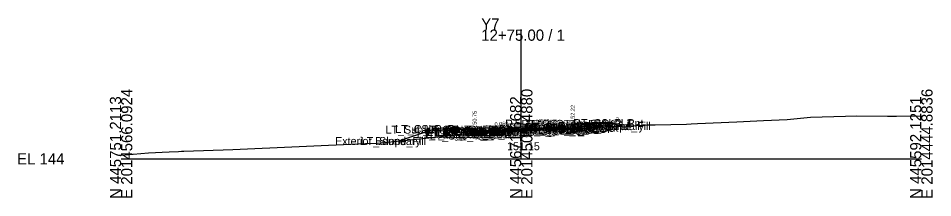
# Model space of a CAD drawing. Extents: x -26 to 203, y -10 to 7527.
# Drawn here: x -25.7 to 202.8, y 5490.3 to 5535.1 of the extents above; entities that cross this region are included whole.
import ezdxf

# ---------------------------------------------------------------- set-up
doc = ezdxf.new("R2010")
doc.units = 0
for name, color, linetype in [('Exist CMT Pavement', 7, 'Continuous'), ('Exist Cross Section Cell', 7, 'Continuous'), ('Exist XS Center Line Elevation Label', 7, 'Continuous'), ('Exist XS Ground Line', 7, 'Continuous'), ('Prop CMT Conc Surface', 7, 'Continuous'), ('Prop CMT Concrete Structures', 7, 'Continuous'), ('Prop CMT Pvmt Course 1', 7, 'Continuous'), ('Prop CMT Pvmt Course 1 CG', 7, 'Continuous'), ('Prop CMT Pvmt Course 1 Wedge', 7, 'Continuous'), ('Prop CMT Pvmt Course 2', 7, 'Continuous'), ('Prop CMT Pvmt Course 2 Wedge', 7, 'Continuous'), ('Prop CMT Pvmt Course 3', 7, 'Continuous'), ('Prop CMT Pvmt Course 3 Wedge', 7, 'Continuous'), ('Prop CMT Pvmt Surface', 7, 'Continuous'), ('Prop CMT Pvmt Wedge Surface 1', 7, 'Continuous'), ('Prop CMT Pvmt Wedge Surface 2', 7, 'Continuous'), ('Prop CMT Pvmt Wedge Surface 3', 7, 'Continuous'), ('Prop CMT Slope Grass', 7, 'Continuous'), ('Prop CMT Subgrade Earthwork', 7, 'Continuous'), ('Prop XS Earthwork Shape', 7, 'Continuous'), ('Prop XS Hydro Elevations', 7, 'Continuous'), ('Prop XS SE Text', 7, 'Continuous'), ('Prop XS Side Slope Text', 7, 'Continuous'), ('Scratch_Level_0', 7, 'Continuous')]:
    doc.layers.add(name, color=color, linetype=linetype)

msp = doc.modelspace()

# ---------------------------------------------------------------- linework, layer by layer
at = {"layer": 'Exist CMT Pavement'}
msp.add_lwpolyline([(91.4, 5506.74), (96.26, 5507.07), (98.92, 5507.12), (100, 5507.15), (101.1, 5507.18), (101.96, 5507.19), (104.5, 5507.18), (107.13, 5507.22)], dxfattribs=at)
at = {"layer": 'Exist Cross Section Cell'}
for p, q in [((100, 5500), (100, 5532.27)), ((0, 5500), (100, 5500)), ((100, 5500), (200, 5500))]:
    msp.add_line(p, q, dxfattribs=at)
at = {"layer": 'Exist XS Ground Line'}
msp.add_lwpolyline([(0, 5500.89), (2.98, 5501.16), (6.88, 5501.48), (12.01, 5501.74), (14.33, 5501.86), (15.1, 5501.89), (15.66, 5501.91), (27.95, 5502.3), (61.07, 5503.8), (63.97, 5503.95), (65.85, 5504.08), (78.42, 5505.37), (87.42, 5506.45), (88.06, 5506.45), (88.69, 5506.55), (96.26, 5507.07), (98.92, 5507.12), (100, 5507.15), (101.1, 5507.18), (101.96, 5507.19), (104.5, 5507.18), (108.95, 5507.25), (113.1, 5507.43), (122.06, 5508.05), (123.08, 5508.08), (124, 5508.12), (130.78, 5508.4), (131.63, 5508.45), (132.27, 5508.47), (133.47, 5508.48), (141.29, 5508.68), (142.47, 5508.73), (144.03, 5508.82), (153.86, 5509.27), (160.53, 5509.53), (166.43, 5509.84), (172.31, 5510.37), (181.08, 5510.68), (183.83, 5510.71), (191.53, 5510.62), (193.76, 5510.64), (200, 5510.76)], dxfattribs=at)
at = {"layer": 'Prop CMT Conc Surface'}
for points in [[(110.88, 5508.18), (112.88, 5508.22)], [(112.88, 5508.22), (112.88, 5508.72), (113.38, 5508.72)], [(88.35, 5506.75), (88.35, 5507.25), (87.85, 5507.25)], [(90.35, 5506.95), (88.35, 5506.75)]]:
    msp.add_lwpolyline(points, dxfattribs=at)
at = {"layer": 'Prop CMT Concrete Structures'}
for points in [[(110.88, 5508.18), (112.88, 5508.22), (112.88, 5508.72), (113.38, 5508.72)], [(113.38, 5508.72), (113.38, 5507.74), (110.88, 5507.59)], [(110.88, 5507.59), (110.88, 5508.18)], [(90.35, 5506.95), (88.35, 5506.75), (88.35, 5507.25), (87.85, 5507.25)], [(87.85, 5507.25), (87.85, 5506.21), (90.35, 5506.36)], [(90.35, 5506.36), (90.35, 5506.95)]]:
    msp.add_lwpolyline(points, dxfattribs=at)
at = {"layer": 'Prop CMT Pvmt Course 1'}
for points in [[(100, 5507.52), (110.88, 5508.18)], [(107.13, 5507.83), (100, 5507.4)], [(110.88, 5507.93), (107.13, 5507.7)], [(107.13, 5507.7), (107.13, 5507.83)], [(110.88, 5508.18), (110.88, 5507.93)], [(100, 5507.52), (90.35, 5506.95)], [(90.35, 5506.95), (90.35, 5506.7)], [(90.35, 5506.7), (91.4, 5506.76)], [(91.4, 5506.88), (100, 5507.4)], [(91.4, 5506.76), (91.4, 5506.88)], [(100, 5507.27), (100, 5507.52)], [(100, 5507.27), (100, 5507.52)], [(100, 5507.4), (100, 5507.27), (100, 5507.27)], [(100, 5507.4), (100, 5507.27), (100, 5507.27)]]:
    msp.add_lwpolyline(points, dxfattribs=at)
at = {"layer": 'Prop CMT Pvmt Course 1 CG'}
for points in [[(110.88, 5507.59), (113.88, 5507.77), (114.19, 5507.46)], [(90.35, 5506.36), (87.35, 5506.18), (87, 5505.83)], [(87, 5505.83), (90.35, 5506.03)], [(90.35, 5506.03), (90.35, 5506.36)], [(110.88, 5507.26), (110.88, 5507.59)], [(114.19, 5507.46), (110.88, 5507.26)]]:
    msp.add_lwpolyline(points, dxfattribs=at)
at = {"layer": 'Prop CMT Pvmt Course 1 Wedge'}
for points in [[(100, 5507.4), (107.13, 5507.83)], [(100, 5507.4), (91.4, 5506.88)]]:
    msp.add_lwpolyline(points, dxfattribs=at)
at = {"layer": 'Prop CMT Pvmt Course 2'}
for points in [[(107.13, 5507.7), (110.88, 5507.93)], [(107.13, 5507.37), (107.13, 5507.7)], [(110.88, 5507.93), (110.88, 5507.59)], [(91.4, 5506.76), (90.35, 5506.7)], [(90.35, 5506.7), (90.35, 5506.36)], [(90.35, 5506.36), (91.4, 5506.43)], [(91.4, 5506.43), (91.4, 5506.76)], [(110.88, 5507.59), (107.13, 5507.37)]]:
    msp.add_lwpolyline(points, dxfattribs=at)
at = {"layer": 'Prop CMT Pvmt Course 2 Wedge'}
for points in [[(100, 5507.27), (107.13, 5507.7)], [(100, 5507.27), (91.4, 5506.76)]]:
    msp.add_lwpolyline(points, dxfattribs=at)
at = {"layer": 'Prop CMT Pvmt Course 3'}
for points in [[(91.4, 5506.43), (90.35, 5506.36)], [(90.35, 5506.36), (90.35, 5506.03)], [(90.35, 5506.03), (91.4, 5506.09)], [(91.4, 5506.09), (91.4, 5506.43)], [(107.13, 5507.37), (110.88, 5507.59)], [(107.13, 5507.04), (107.13, 5507.37)], [(110.88, 5507.26), (107.13, 5507.04)], [(110.88, 5507.59), (110.88, 5507.26)]]:
    msp.add_lwpolyline(points, dxfattribs=at)
at = {"layer": 'Prop CMT Pvmt Course 3 Wedge'}
for points in [[(100, 5506.94), (91.4, 5506.43)], [(100, 5506.94), (107.13, 5507.37)]]:
    msp.add_lwpolyline(points, dxfattribs=at)
at = {"layer": 'Prop CMT Pvmt Surface'}
for points in [[(100, 5507.52), (110.88, 5508.18)], [(100, 5507.52), (90.35, 5506.95)]]:
    msp.add_lwpolyline(points, dxfattribs=at)
at = {"layer": 'Prop CMT Pvmt Wedge Surface 1'}
for points in [[(100, 5507.4), (107.13, 5507.83)], [(107.13, 5507.7), (110.88, 5507.93)], [(107.13, 5507.83), (107.13, 5507.7)], [(110.88, 5507.93), (110.88, 5508.18)], [(90.35, 5506.7), (90.35, 5506.95)], [(91.4, 5506.76), (90.35, 5506.7)], [(100, 5507.4), (91.4, 5506.88)], [(91.4, 5506.88), (91.4, 5506.76)]]:
    msp.add_lwpolyline(points, dxfattribs=at)
at = {"layer": 'Prop CMT Pvmt Wedge Surface 2'}
for points in [[(100, 5507.27), (110.88, 5507.93)], [(110.88, 5507.93), (110.88, 5508.18)], [(100, 5507.27), (90.35, 5506.7)], [(90.35, 5506.7), (90.35, 5506.95)]]:
    msp.add_lwpolyline(points, dxfattribs=at)
at = {"layer": 'Prop CMT Pvmt Wedge Surface 3'}
for points in [[(110.88, 5507.59), (110.88, 5508.18)], [(90.35, 5506.36), (90.35, 5506.95)], [(100, 5506.94), (90.35, 5506.36)], [(100, 5506.94), (110.88, 5507.59)]]:
    msp.add_lwpolyline(points, dxfattribs=at)
at = {"layer": 'Prop CMT Slope Grass'}
for points in [[(113.38, 5508.72), (122.88, 5508.91), (125.1, 5508.17)], [(87.85, 5507.25), (78.35, 5507.44), (69.36, 5504.44)]]:
    msp.add_lwpolyline(points, dxfattribs=at)
at = {"layer": 'Prop CMT Subgrade Earthwork'}
for points in [[(110.88, 5507.26), (114.19, 5507.46), (115.5, 5508.76)], [(90.35, 5506.03), (87, 5505.83), (85.53, 5507.29)], [(91.4, 5506.09), (90.35, 5506.03)], [(91.4, 5506.09), (91.4, 5506.74)], [(107.13, 5507.04), (110.88, 5507.26)], [(107.13, 5507.04), (107.13, 5507.22)]]:
    msp.add_lwpolyline(points, dxfattribs=at)
at = {"layer": 'Prop XS Earthwork Shape'}
for points in [[(122.06, 5508.05), (123.08, 5508.08), (124, 5508.12), (125.1, 5508.17), (122.88, 5508.91), (115.5, 5508.76), (114.25, 5507.51)], [(69.36, 5504.44), (78.42, 5505.37), (86.48, 5506.34), (85.53, 5507.29), (78.35, 5507.44)], [(87.85, 5506.45), (87.85, 5506.21), (90.35, 5506.36), (90.35, 5506.67), (91.4, 5506.74), (91.4, 5506.09), (90.35, 5506.03), (87, 5505.83), (86.48, 5506.34), (87.42, 5506.45)], [(87.85, 5506.45), (87.85, 5506.21), (90.35, 5506.36), (90.35, 5506.67), (88.69, 5506.55), (88.06, 5506.45)], [(113.1, 5507.43), (114.25, 5507.51), (114.19, 5507.46), (110.88, 5507.26), (107.13, 5507.04), (107.13, 5507.22), (108.95, 5507.25)]]:
    msp.add_lwpolyline(points, close=True, dxfattribs=at)

# ---------------------------------------------------------------- texts
at = {"layer": 'Exist Cross Section Cell'}
for s, p in [('Y7', (90, 5532.27)), ('12+75.00 / 1', (90, 5529.47)), ('EL 144', (-26, 5498.6))]:
    msp.add_text(s, height=2.8, dxfattribs=at).set_placement(p)
for s, p in [('E 2014566.0924', (2.8, 5490)), ('E 2014505.4880', (102.8, 5490)), ('E 2014444.8836', (202.8, 5490)), ('N 445751.2113', (0, 5490)), ('N 445671.6682', (100, 5490)), ('N 445592.1251', (200, 5490))]:
    msp.add_text(s, height=2.8, rotation=90, dxfattribs=at).set_placement(p)
at = {"layer": 'Exist XS Center Line Elevation Label'}
msp.add_text('151.15', height=2, dxfattribs=at).set_placement((96.46, 5502.15))
at = {"layer": 'Prop XS Hydro Elevations'}
for s, p in [('152.22', (113.38, 5509.22)), ('150.75', (88.85, 5507.75))]:
    msp.add_text(s, height=1, rotation=90, dxfattribs=at).set_placement(p)
at = {"layer": 'Prop XS SE Text'}
for p in [(103.63, 5508.74), (93.37, 5508.13)]:
    msp.add_text('0.060', height=1, rotation=3.4336, dxfattribs=at).set_placement(p)
at = {"layer": 'Prop XS Side Slope Text'}
for rotation, p in [(341.5668, (123.48, 5509.5)), (18.4332, (72.86, 5506.4))]:
    msp.add_text('3:1', height=1, rotation=rotation, dxfattribs=at).set_placement(p)
at = {"layer": 'Scratch_Level_0'}
for s, p in [('RT_CSLP_Pnt', (113.01, 5507.91)), ('LT_Sub_Trench_Out_DLT', (66.1, 5506.29)), ('LT_CSLP_Pnt', (68.52, 5506.44)), ('LT_CG_Top_Face', (75.61, 5506.25)), ('LT_CG_Top_BOC', (76.13, 5506.25)), ('LT_PV_Sub_Tie_Out', (76.36, 5505.74)), ('LT_CG_Top_Gut', (76.59, 5505.75)), ('LT_PV_OEEOP_EG', (78.94, 5505.74)), ('LT_PV2_OEOT', (80.52, 5505.7)), ('LT_PV2_OEEOP', (80.71, 5505.76)), ('LT_PV1_OEOT', (81.09, 5505.95)), ('LT_PV1_OEEOP', (81.27, 5505.88)), ('RT_PV_IEEOP_EG', (88.14, 5506.15)), ('LT_PV_IEEOP_EG', (88.19, 5506.15)), ('RT_PV2_IEEOP', (89.91, 5506.27)), ('RT_PV3_IEEOP', (89.91, 5505.94)), ('LT_PV2_IEEOP', (89.95, 5506.27)), ('LT_PV3_IEEOP', (89.95, 5505.94)), ('RT_PV1_IEEOP', (90.47, 5506.4)), ('LT_PV1_IEEOP', (90.52, 5506.4)), ('RT_PV_Sub_Tie_Out', (92.01, 5506.22)), ('PV2_PGL', (93.91, 5506.27)), ('PV1_PGL', (94.47, 5506.52)), ('RT_PV_OEEOP_EG', (94.63, 5506.22)), ('RT_Sub_Trench_Out_DLT', (96.01, 5507.76)), ('RT_Sub_OEEOP', (96.3, 5506.04)), ('RT_PV2_OEEOP', (96.39, 5506.7)), ('RT_PV3_OEEOP', (96.39, 5506.37)), ('RT_PV1_OEEOP', (96.96, 5506.83)), ('RT_CG_Top_Face', (100.09, 5507.72)), ('RT_CG1_Shelf_Out', (100.38, 5506.77)), ('RT_CG_Bot_IE', (100.75, 5506.59)), ('RT_Sub_OEOT', (100.91, 5506.26)), ('RT_PV2_OEOT', (101.01, 5506.93)), ('RT_PV3_OEOT', (101.01, 5506.59)), ('RT_CG_Top_Gut', (101.07, 5507.22)), ('RT_PV1_OEOT', (101.57, 5507.18)), ('RT_CG_Top_BOC', (101.62, 5507.72)), ('RT_CG_Bot_BOC', (101.65, 5506.74)), ('RT_Sub_OEOP', (104.26, 5506.46)), ('Exterior Boundary', (109.25, 5507.17)), ('RT_Slope_Fill', (115.58, 5507.17)), ('Exterior Boundary', (53.49, 5503.44)), ('LT_Slope_Fill', (59.87, 5503.44)), ('LT_CG1_Shelf_Out', (73.9, 5505.18)), ('LT_CG_Bot_BOC', (76.17, 5505.21)), ('LT_Sub_OEOP', (77.11, 5504.83)), ('LT_CG_Bot_IE', (80.26, 5505.36)), ('LT_Sub_OEOT', (80.43, 5505.03)), ('LT_PV3_OEOT', (80.52, 5505.36)), ('LT_Sub_OEEOP', (80.61, 5505.09)), ('LT_PV3_OEEOP', (80.71, 5505.43))]:
    msp.add_text(s, height=2, dxfattribs=at).set_placement(p)

doc.saveas('drawing.dxf')
